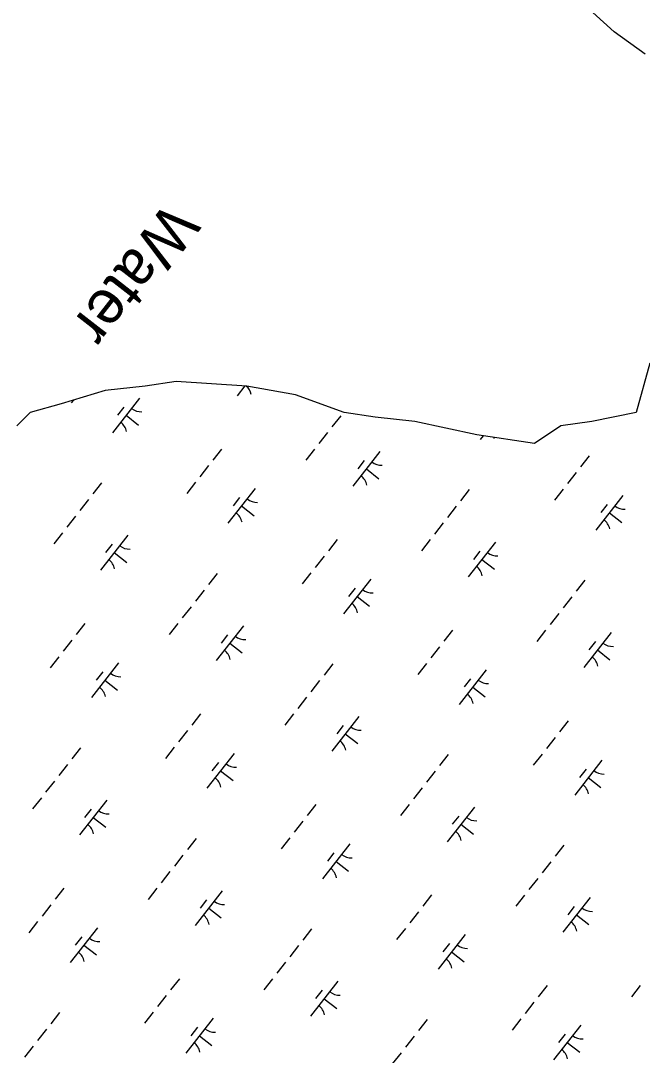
# Model space of a CAD drawing. Extents: x 3896831 to 3918110, y 171006 to 193349.
# Drawn here: x 3908693 to 3909397, y 185832 to 187004 of the extents above; entities that cross this region are included whole.
import ezdxf

# ---------------------------------------------------------------- set-up
doc = ezdxf.new("R2010")
doc.units = 0
doc.layers.add('V-RIVR-IDEN', color=7, linetype='Continuous')
doc.layers.add('V-WETL-SWMP', color=7, linetype='Continuous')

msp = doc.modelspace()

# ---------------------------------------------------------------- linework, layer by layer
at = {"layer": 'V-WETL-SWMP'}
for p, q in [((3909405.7, 186616.2), (3909390, 186560.4)), ((3908788.5, 186585.4), (3908738.4, 186570.4)), ((3908833.6, 186590.5), (3908788.5, 186585.4)), ((3908868.7, 186595.5), (3908833.6, 186590.5)), ((3908948.9, 186590.5), (3908868.7, 186595.5)), ((3908946.7, 186590.6), (3908938.1, 186579.5)), ((3909004.1, 186580.4), (3908948.9, 186590.5)), ((3908752.4, 186574.6), (3908749.8, 186571.4)), ((3908827.5, 186576.9), (3908796.7, 186537.6)), ((3909059.2, 186560.4), (3909004.1, 186580.4)), ((3908738.4, 186570.4), (3908703.3, 186560.4)), ((3908809.7, 186566.7), (3908802.3, 186557.3)), ((3908703.3, 186560.4), (3908688.3, 186545.3)), ((3908812.1, 186557.3), (3908826.3, 186546.2)), ((3909055.3, 186556.8), (3909045.4, 186544.2)), ((3909094.3, 186555.3), (3909059.2, 186560.4)), ((3909139.4, 186550.3), (3909094.3, 186555.3)), ((3909209.6, 186535.3), (3909139.4, 186550.3)), ((3909339.9, 186550.3), (3909304.8, 186545.3)), ((3909390, 186560.4), (3909339.9, 186550.3)), ((3909040.5, 186537.9), (3909030.6, 186525.3)), ((3909304.8, 186545.3), (3909274.8, 186525.3)), ((3909274.8, 186525.3), (3909209.6, 186535.3)), ((3909216.7, 186534.2), (3909213.3, 186529.9)), ((3908920.2, 186519.1), (3908910.4, 186506.5)), ((3909025.7, 186519), (3909015.8, 186506.4)), ((3909099.8, 186516.3), (3909069, 186476.9)), ((3909082, 186506.1), (3909074.6, 186496.6)), ((3909336.9, 186511.4), (3909327, 186498.8)), ((3908905.4, 186500.3), (3908895.6, 186487.7)), ((3909084.4, 186496.6), (3909098.6, 186485.5)), ((3909322.1, 186492.6), (3909312.2, 186480)), ((3908784.4, 186480.8), (3908774.5, 186468.2)), ((3908890.6, 186481.4), (3908880.8, 186468.8)), ((3908958.5, 186474.3), (3908927.6, 186435)), ((3909201, 186473.1), (3909191.2, 186460.5)), ((3909307.3, 186473.7), (3909297.4, 186461.1)), ((3908769.6, 186461.9), (3908759.7, 186449.3)), ((3908940.7, 186464.1), (3908933.3, 186454.7)), ((3909375.1, 186466.6), (3909344.3, 186427.3)), ((3909357.3, 186456.4), (3909349.9, 186447)), ((3908943, 186454.6), (3908957.2, 186443.5)), ((3909186.2, 186454.2), (3909176.4, 186441.6)), ((3909359.7, 186446.9), (3909373.8, 186435.8)), ((3908754.8, 186443), (3908744.9, 186430.4)), ((3909171.4, 186435.3), (3909161.6, 186422.7)), ((3908740, 186424.1), (3908730.1, 186411.5)), ((3908814.1, 186421.4), (3908783.3, 186382)), ((3908796.3, 186411.2), (3908788.9, 186401.7)), ((3909051.2, 186416.5), (3909041.3, 186403.9)), ((3909156.6, 186416.4), (3909146.8, 186403.8)), ((3909230.8, 186413.7), (3909199.9, 186374.3)), ((3908798.7, 186401.7), (3908812.9, 186390.6)), ((3909036.4, 186397.6), (3909026.5, 186385)), ((3909213, 186403.5), (3909205.6, 186394)), ((3909215.3, 186394), (3909229.5, 186382.9)), ((3908915.3, 186378.2), (3908905.4, 186365.6)), ((3909021.6, 186378.8), (3909011.7, 186366.2)), ((3909089.4, 186371.7), (3909058.5, 186332.4)), ((3909332, 186370.5), (3909322.1, 186357.9)), ((3908900.5, 186359.3), (3908890.6, 186346.7)), ((3909071.6, 186361.5), (3909064.2, 186352.1)), ((3909073.9, 186352), (3909088.1, 186340.9)), ((3909317.2, 186351.6), (3909307.3, 186339)), ((3908885.7, 186340.4), (3908875.8, 186327.8)), ((3909302.3, 186332.7), (3909292.5, 186320.1)), ((3908765.4, 186321.6), (3908755.6, 186309)), ((3908870.9, 186321.5), (3908861, 186308.9)), ((3908945, 186318.8), (3908914.2, 186279.4)), ((3908927.2, 186308.6), (3908919.8, 186299.1)), ((3909182.1, 186313.9), (3909172.2, 186301.3)), ((3909287.5, 186313.8), (3909277.7, 186301.2)), ((3909361.7, 186311.1), (3909330.8, 186271.7)), ((3908750.6, 186302.7), (3908740.8, 186290.1)), ((3908929.6, 186299.1), (3908943.8, 186288)), ((3909167.3, 186295), (3909157.4, 186282.4)), ((3909343.9, 186300.9), (3909336.5, 186291.4)), ((3909346.3, 186291.4), (3909360.4, 186280.3)), ((3908735.8, 186283.8), (3908726, 186271.3)), ((3908803.6, 186276.8), (3908772.8, 186237.5)), ((3909046.2, 186275.6), (3909036.4, 186263)), ((3909152.5, 186276.1), (3909142.6, 186263.6)), ((3909220.3, 186269.1), (3909189.4, 186229.8)), ((3908785.9, 186266.6), (3908778.4, 186257.2)), ((3908788.2, 186257.1), (3908802.4, 186246)), ((3909031.4, 186256.7), (3909021.6, 186244.1)), ((3909202.5, 186258.9), (3909195.1, 186249.5)), ((3909204.9, 186249.4), (3909219, 186238.3)), ((3909016.6, 186237.8), (3909006.8, 186225.2)), ((3908896.4, 186219), (3908886.5, 186206.4)), ((3909001.8, 186218.9), (3908992, 186206.3)), ((3909076, 186216.1), (3909045.1, 186176.8)), ((3909313, 186211.3), (3909303.1, 186198.7)), ((3908881.6, 186200.1), (3908871.7, 186187.5)), ((3909058.2, 186206), (3909050.8, 186196.5)), ((3909060.5, 186196.5), (3909074.7, 186185.4)), ((3909298.2, 186192.4), (3909288.3, 186179.8)), ((3908760.5, 186180.6), (3908750.6, 186168.1)), ((3908866.7, 186181.2), (3908856.9, 186168.6)), ((3908934.6, 186174.2), (3908903.7, 186134.8)), ((3908916.8, 186164), (3908909.4, 186154.6)), ((3909177.2, 186172.9), (3909167.3, 186160.4)), ((3909283.4, 186173.5), (3909273.5, 186160.9)), ((3909351.2, 186166.5), (3909320.4, 186127.1)), ((3908745.7, 186161.8), (3908735.8, 186149.2)), ((3908919.1, 186154.5), (3908933.3, 186143.4)), ((3909162.3, 186154.1), (3909152.5, 186141.5)), ((3909333.4, 186156.3), (3909326, 186146.9)), ((3908730.9, 186142.9), (3908721, 186130.3)), ((3909335.8, 186146.8), (3909350, 186135.7)), ((3909147.5, 186135.2), (3909137.7, 186122.6)), ((3908716.1, 186124), (3908706.2, 186111.4)), ((3908790.2, 186121.2), (3908759.4, 186081.9)), ((3909027.3, 186116.4), (3909017.4, 186103.8)), ((3909132.7, 186116.3), (3909122.9, 186103.7)), ((3908772.4, 186111), (3908765, 186101.6)), ((3909206.9, 186113.5), (3909176, 186074.2)), ((3908774.8, 186101.6), (3908789, 186090.5)), ((3909012.5, 186097.5), (3909002.6, 186084.9)), ((3909189.1, 186103.3), (3909181.7, 186093.9)), ((3909191.5, 186093.9), (3909205.6, 186082.8)), ((3908891.4, 186078), (3908881.6, 186065.4)), ((3908997.7, 186078.6), (3908987.8, 186066)), ((3909065.5, 186071.6), (3909034.6, 186032.2)), ((3909308.1, 186070.3), (3909298.2, 186057.7)), ((3908876.6, 186059.1), (3908866.8, 186046.6)), ((3909047.7, 186061.4), (3909040.3, 186052)), ((3909050.1, 186051.9), (3909064.2, 186040.8)), ((3909293.3, 186051.4), (3909283.4, 186038.9)), ((3908861.8, 186040.3), (3908851.9, 186027.7)), ((3909278.5, 186032.6), (3909268.6, 186020)), ((3908741.6, 186021.5), (3908731.7, 186008.9)), ((3908847, 186021.4), (3908837.1, 186008.8)), ((3908921.1, 186018.6), (3908890.3, 185979.3)), ((3909158.2, 186013.8), (3909148.3, 186001.2)), ((3909263.7, 186013.7), (3909253.8, 186001.1)), ((3909337.8, 186010.9), (3909306.9, 185971.6)), ((3908726.7, 186002.6), (3908716.9, 185990)), ((3908903.4, 186008.4), (3908896, 185999)), ((3908905.7, 185999), (3908919.9, 185987.9)), ((3909320, 186000.7), (3909312.6, 185991.3)), ((3909143.4, 185994.9), (3909133.5, 185982.3)), ((3909322.4, 185991.3), (3909336.5, 185980.2)), ((3908711.9, 185983.7), (3908702.1, 185971.1)), ((3908779.8, 185976.7), (3908748.9, 185937.3)), ((3909022.3, 185975.4), (3909012.5, 185962.8)), ((3909128.6, 185976), (3909118.7, 185963.4)), ((3908762, 185966.5), (3908754.6, 185957)), ((3909196.4, 185969), (3909165.6, 185929.6)), ((3908764.3, 185957), (3908778.5, 185945.9)), ((3909007.5, 185956.5), (3908997.7, 185943.9)), ((3909178.6, 185958.8), (3909171.2, 185949.3)), ((3909181, 185949.3), (3909195.1, 185938.2)), ((3908992.7, 185937.6), (3908982.9, 185925.1)), ((3908872.5, 185918.9), (3908862.6, 185906.3)), ((3908977.9, 185918.8), (3908968.1, 185906.2)), ((3909052.1, 185916), (3909021.2, 185876.7)), ((3909034.3, 185905.8), (3909026.9, 185896.4)), ((3909289.1, 185911.2), (3909279.2, 185898.6)), ((3909394.6, 185911.1), (3909384.7, 185898.5)), ((3908857.7, 185900), (3908847.8, 185887.4)), ((3909036.6, 185896.3), (3909050.8, 185885.2)), ((3908842.9, 185881.1), (3908833, 185868.5)), ((3909274.3, 185892.3), (3909264.4, 185879.7)), ((3908736.6, 185880.5), (3908726.8, 185867.9)), ((3908910.7, 185874.1), (3908879.8, 185834.7)), ((3909153.3, 185872.8), (3909143.4, 185860.2)), ((3909259.5, 185873.4), (3909249.6, 185860.8)), ((3908721.8, 185861.6), (3908711.9, 185849)), ((3908892.9, 185863.9), (3908885.5, 185854.4)), ((3909327.3, 185866.4), (3909296.5, 185827)), ((3908895.3, 185854.4), (3908909.4, 185843.3)), ((3909138.5, 185853.9), (3909128.6, 185841.3)), ((3909309.5, 185856.2), (3909302.1, 185846.7)), ((3909311.9, 185846.7), (3909326.1, 185835.6)), ((3908707, 185842.7), (3908697.1, 185830.1)), ((3909123.7, 185835), (3909113.8, 185822.4))]:
    msp.add_line(p, q, dxfattribs=at)
msp.add_lwpolyline([(3909400.1, 186966.6), (3909365, 186991.7), (3909304.8, 187046.9)], dxfattribs=at)
for centre, start, end in [((3908936.6, 186577.3), 11.1403, 48.3387), ((3908829.3, 186578.9), 231.1403, 272.6839), ((3908795.3, 186535.4), 11.1403, 52.6839), ((3909211.9, 186527.7), 11.1403, 15.2552), ((3909101.6, 186518.2), 231.1403, 272.6839), ((3909067.6, 186474.7), 11.1403, 52.6839), ((3908960.3, 186476.2), 231.1403, 272.6839), ((3908926.2, 186432.8), 11.1403, 52.6839), ((3909376.9, 186468.5), 231.1403, 272.6839), ((3909342.8, 186425.1), 11.1403, 52.6839), ((3908815.9, 186423.3), 231.1403, 272.6839), ((3909232.6, 186415.6), 231.1403, 272.6839), ((3908781.8, 186379.8), 11.1403, 52.6839), ((3909198.5, 186372.1), 11.1403, 52.6839), ((3909091.2, 186373.6), 231.1403, 272.6839), ((3909057.1, 186330.2), 11.1403, 52.6839), ((3908946.8, 186320.7), 231.1403, 272.6839), ((3909363.5, 186313), 231.1403, 272.6839), ((3908912.8, 186277.2), 11.1403, 52.6839), ((3909329.4, 186269.5), 11.1403, 52.6839), ((3908805.4, 186278.7), 231.1403, 272.6839), ((3909222.1, 186271), 231.1403, 272.6839), ((3908771.4, 186235.2), 11.1403, 52.6839), ((3909188, 186227.5), 11.1403, 52.6839), ((3909077.8, 186218.1), 231.1403, 272.6839), ((3909043.7, 186174.6), 11.1403, 52.6839), ((3908936.4, 186176.1), 231.1403, 272.6839), ((3909353, 186168.4), 231.1403, 272.6839), ((3908902.3, 186132.6), 11.1403, 52.6839), ((3909318.9, 186124.9), 11.1403, 52.6839), ((3908792, 186123.2), 231.1403, 272.6839), ((3908758, 186079.7), 11.1403, 52.6839), ((3909208.7, 186115.5), 231.1403, 272.6839), ((3909174.6, 186072), 11.1403, 52.6839), ((3909067.3, 186073.5), 231.1403, 272.6839), ((3909033.2, 186030), 11.1403, 52.6839), ((3908923, 186020.5), 231.1403, 272.6839), ((3909339.6, 186012.8), 231.1403, 272.6839), ((3908888.9, 185977.1), 11.1403, 52.6839), ((3909305.5, 185969.4), 11.1403, 52.6839), ((3908781.6, 185978.6), 231.1403, 272.6839), ((3909198.2, 185970.9), 231.1403, 272.6839), ((3908747.5, 185935.1), 11.1403, 52.6839), ((3909164.1, 185927.4), 11.1403, 52.6839), ((3909053.9, 185917.9), 231.1403, 272.6839), ((3909019.8, 185874.5), 11.1403, 52.6839), ((3908912.5, 185876), 231.1403, 272.6839), ((3908878.4, 185832.5), 11.1403, 52.6839), ((3909329.1, 185868.3), 231.1403, 272.6839), ((3909295, 185824.8), 11.1403, 52.6839)]:
    msp.add_arc(centre, 17.6, start, end, dxfattribs=at)

# ---------------------------------------------------------------- texts
at = {"layer": 'V-RIVR-IDEN'}
msp.add_text('Water', height=50, rotation=232.0843, dxfattribs=at).set_placement((3908858.6, 186800.9))

doc.saveas('drawing.dxf')
